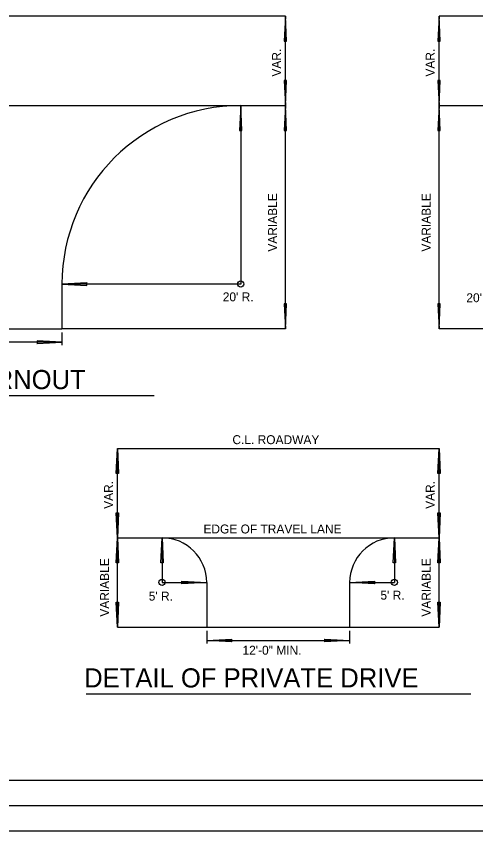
# Model space of a CAD drawing. Extents: x 1944905 to 1956777, y 763871 to 764977.
# Drawn here: x 1947213 to 1947573, y 763871 to 764509 of the extents above; entities that cross this region are included whole.
import ezdxf

# ---------------------------------------------------------------- set-up
doc = ezdxf.new("R2010")
doc.units = 0
doc.layers.add('Default', color=7, linetype='Continuous')
doc.layers.add('E_Existing ROW', color=7, linetype='Continuous')

msp = doc.modelspace()

# ---------------------------------------------------------------- linework, layer by layer
at = {"layer": 'Default'}
for p, q in [((1947423.48, 764509.29), (1946821.48, 764509.29)), ((1947423.48, 764509.29), (1947422.51, 764489.74)), ((1947423.48, 764439.29), (1947423.48, 764509.29)), ((1947424.46, 764489.74), (1947423.48, 764509.29)), ((1947543.85, 764509.29), (1947542.88, 764489.74)), ((1948061.85, 764509.29), (1947543.85, 764509.29)), ((1947543.85, 764439.29), (1947543.85, 764509.29)), ((1947544.83, 764489.74), (1947543.85, 764509.29)), ((1947422.51, 764489.74), (1947424.46, 764489.74)), ((1947424.46, 764489.68), (1947424.46, 764489.74)), ((1947542.88, 764489.74), (1947544.83, 764489.74)), ((1947544.83, 764489.68), (1947544.83, 764489.74)), ((1947422.51, 764458.9), (1947422.51, 764458.84)), ((1947422.51, 764458.84), (1947423.48, 764439.29)), ((1947424.46, 764458.84), (1947422.51, 764458.84)), ((1947423.48, 764439.29), (1947424.46, 764458.84)), ((1947542.88, 764458.9), (1947542.88, 764458.84)), ((1947542.88, 764458.84), (1947543.85, 764439.29)), ((1947544.83, 764458.84), (1947542.88, 764458.84)), ((1947543.85, 764439.29), (1947544.83, 764458.84)), ((1946856.48, 764439.29), (1947388.48, 764439.29)), ((1947388.48, 764439.29), (1947387.51, 764419.74)), ((1947389.46, 764419.74), (1947388.48, 764439.29)), ((1947388.48, 764439.29), (1947388.48, 764299.29)), ((1947423.48, 764439.29), (1947422.51, 764419.74)), ((1947424.46, 764419.74), (1947423.48, 764439.29)), ((1947423.48, 764264.29), (1947423.48, 764438.7)), ((1947543.85, 764439.29), (1947542.88, 764419.74)), ((1947544.83, 764419.74), (1947543.85, 764439.29)), ((1947543.85, 764264.29), (1947543.85, 764438.7)), ((1947387.51, 764419.74), (1947389.46, 764419.74)), ((1947389.46, 764419.68), (1947389.46, 764419.74)), ((1947422.51, 764419.74), (1947424.46, 764419.74)), ((1947424.46, 764419.68), (1947424.46, 764419.74)), ((1947542.88, 764419.74), (1947544.83, 764419.74)), ((1947544.83, 764419.68), (1947544.83, 764419.74)), ((1947268.03, 764300.27), (1947248.48, 764299.29)), ((1947388.48, 764299.29), (1947248.48, 764299.29)), ((1947248.48, 764299.29), (1947268.03, 764298.31)), ((1947268.03, 764298.31), (1947268.03, 764300.27)), ((1947268.1, 764300.27), (1947268.03, 764300.27)), ((1947422.51, 764283.9), (1947422.51, 764283.84)), ((1947422.51, 764283.84), (1947423.48, 764264.29)), ((1947424.46, 764283.84), (1947422.51, 764283.84)), ((1947423.48, 764264.29), (1947424.46, 764283.84)), ((1947542.88, 764283.9), (1947542.88, 764283.84)), ((1947542.88, 764283.84), (1947543.85, 764264.29)), ((1947544.83, 764283.84), (1947542.88, 764283.84)), ((1947543.85, 764264.29), (1947544.83, 764283.84)), ((1946996.48, 764264.29), (1947248.48, 764264.29)), ((1947423.48, 764264.29), (1947248.48, 764264.29)), ((1947718.85, 764264.29), (1947543.85, 764264.29)), ((1947248.48, 764261.29), (1947248.48, 764251.51)), ((1947248.48, 764253.76), (1946996.48, 764253.76)), ((1947228.87, 764252.78), (1947228.94, 764252.78)), ((1947248.48, 764253.76), (1947228.94, 764254.74)), ((1947228.94, 764254.74), (1947228.94, 764252.78)), ((1947228.94, 764252.78), (1947248.48, 764253.76)), ((1946925.27, 764211.94), (1947320.65, 764211.94)), ((1947290.88, 764150.79), (1947291.85, 764170.34)), ((1947291.85, 764170.34), (1947543.85, 764170.34)), ((1947291.85, 764100.34), (1947291.85, 764170.34)), ((1947291.85, 764170.34), (1947292.83, 764150.79)), ((1947542.88, 764150.79), (1947543.85, 764170.34)), ((1947543.85, 764100.34), (1947543.85, 764170.34)), ((1947543.85, 764170.34), (1947544.83, 764150.79)), ((1947292.83, 764150.79), (1947290.88, 764150.79)), ((1947290.88, 764150.73), (1947290.88, 764150.79)), ((1947544.83, 764150.79), (1947542.88, 764150.79)), ((1947542.88, 764150.73), (1947542.88, 764150.79)), ((1947291.85, 764100.34), (1947290.88, 764119.89)), ((1947290.88, 764119.89), (1947292.83, 764119.89)), ((1947292.83, 764119.89), (1947291.85, 764100.34)), ((1947292.83, 764119.95), (1947292.83, 764119.89)), ((1947543.85, 764100.34), (1947542.88, 764119.89)), ((1947542.88, 764119.89), (1947544.83, 764119.89)), ((1947544.83, 764119.89), (1947543.85, 764100.34)), ((1947544.83, 764119.95), (1947544.83, 764119.89)), ((1947290.88, 764080.79), (1947291.85, 764100.34)), ((1947291.85, 764100.34), (1947292.83, 764080.79)), ((1947291.85, 764030.34), (1947291.85, 764099.75)), ((1947325.88, 764080.79), (1947326.85, 764100.34)), ((1947326.85, 764100.34), (1947508.85, 764100.34)), ((1947326.85, 764100.34), (1947327.83, 764080.79)), ((1947326.85, 764100.34), (1947326.85, 764065.34)), ((1947507.88, 764080.79), (1947508.85, 764100.34)), ((1947508.85, 764100.34), (1947508.85, 764065.34)), ((1947508.85, 764100.34), (1947509.83, 764080.79)), ((1947542.88, 764080.79), (1947543.85, 764100.34)), ((1947543.85, 764100.34), (1947544.83, 764080.79)), ((1947543.85, 764030.34), (1947543.85, 764099.75)), ((1947292.83, 764080.79), (1947290.88, 764080.79)), ((1947290.88, 764080.73), (1947290.88, 764080.79)), ((1947327.83, 764080.79), (1947325.88, 764080.79)), ((1947325.88, 764080.73), (1947325.88, 764080.79)), ((1947509.83, 764080.79), (1947507.88, 764080.79)), ((1947507.88, 764080.73), (1947507.88, 764080.79)), ((1947544.83, 764080.79), (1947542.88, 764080.79)), ((1947542.88, 764080.73), (1947542.88, 764080.79)), ((1947326.85, 764065.34), (1947361.85, 764065.34)), ((1947342.24, 764066.32), (1947342.31, 764066.32)), ((1947342.31, 764066.32), (1947361.85, 764065.34)), ((1947342.31, 764064.36), (1947342.31, 764066.32)), ((1947361.85, 764065.34), (1947342.31, 764064.36)), ((1947473.85, 764065.34), (1947493.4, 764066.32)), ((1947473.85, 764065.34), (1947508.85, 764065.34)), ((1947493.4, 764064.36), (1947473.85, 764065.34)), ((1947493.4, 764066.32), (1947493.4, 764064.36)), ((1947493.47, 764064.36), (1947493.4, 764064.36)), ((1947291.85, 764030.34), (1947290.88, 764049.89)), ((1947290.88, 764049.89), (1947292.83, 764049.89)), ((1947292.83, 764049.89), (1947291.85, 764030.34)), ((1947292.83, 764049.95), (1947292.83, 764049.89)), ((1947543.85, 764030.34), (1947542.88, 764049.89)), ((1947542.88, 764049.89), (1947544.83, 764049.89)), ((1947544.83, 764049.89), (1947543.85, 764030.34)), ((1947544.83, 764049.95), (1947544.83, 764049.89)), ((1947291.85, 764030.34), (1947361.85, 764030.34)), ((1947361.85, 764030.34), (1947473.85, 764030.34)), ((1947361.85, 764027.35), (1947361.85, 764017.56)), ((1947473.85, 764030.34), (1947543.85, 764030.34)), ((1947473.85, 764027.35), (1947473.85, 764017.56)), ((1947361.85, 764019.81), (1947381.4, 764020.79)), ((1947381.4, 764018.83), (1947361.85, 764019.81)), ((1947361.85, 764019.81), (1947473.85, 764019.81)), ((1947381.4, 764020.79), (1947381.4, 764018.83)), ((1947454.24, 764020.79), (1947454.31, 764020.79)), ((1947454.31, 764020.79), (1947473.85, 764019.81)), ((1947454.31, 764018.83), (1947454.31, 764020.79)), ((1947473.85, 764019.81), (1947454.31, 764018.83)), ((1947381.47, 764018.83), (1947381.4, 764018.83)), ((1947267.35, 763978), (1947568.77, 763978)), ((1948232.12, 763910.07), (1946651.22, 763910.07)), ((1946618.38, 763890.36), (1948232.12, 763890.36)), ((1946618.38, 763870.67), (1948232.12, 763870.67))]:
    msp.add_line(p, q, dxfattribs=at)
for centre in [(1947388.48, 764299.29), (1947326.85, 764065.34), (1947508.85, 764065.34)]:
    msp.add_circle(centre, 2.44, dxfattribs=at)
at = {"layer": 'E_Existing ROW'}
for p, q in [((1947388.48, 764439.29), (1947423.48, 764439.29)), ((1947543.85, 764439.29), (1947578.85, 764439.29)), ((1947248.48, 764299.29), (1947248.48, 764264.29)), ((1947291.85, 764100.34), (1947326.85, 764100.34)), ((1947508.85, 764100.34), (1947543.85, 764100.34)), ((1947361.85, 764065.34), (1947361.85, 764030.34)), ((1947473.85, 764065.34), (1947473.85, 764030.34))]:
    msp.add_line(p, q, dxfattribs=at)
for centre, radius, start, end in [((1947388.48, 764299.29), 140, 90, 180), ((1947326.85, 764065.34), 35, 0, 90), ((1947508.85, 764065.34), 35, 90, 180)]:
    msp.add_arc(centre, radius, start, end, dxfattribs=at)

# ---------------------------------------------------------------- texts
at = {"layer": 'Default'}
for s, p in [('VAR.', (1947420.06, 764462.01)), ('VAR.', (1947540.43, 764462.01)), ('VARIABLE', (1947416.94, 764324.75)), ('VARIABLE', (1947537.31, 764324.75)), ('VAR.', (1947288.43, 764123.06)), ('VAR.', (1947540.43, 764123.06)), ('VARIABLE', (1947285.31, 764038.5)), ('VARIABLE', (1947537.31, 764038.5))]:
    msp.add_text(s, height=7, rotation=90, dxfattribs=at).set_placement(p)
for s, height, p in [("20' R.", 7, (1947374.43, 764285.79)), ("20' R.", 7, (1947565.27, 764285.09)), ('DETAIL OF CITY STREET TURNOUT', 15, (1946923.81, 764216.94)), ('C.L. ROADWAY', 7, (1947381.98, 764173.79)), ('EDGE OF TRAVEL LANE', 7, (1947359.28, 764103.76)), ("5' R.", 7, (1947316.44, 764051.14)), ("5' R.", 7, (1947497.97, 764051.85)), ('12\'-0" MIN.', 7, (1947389.89, 764008.71)), ('DETAIL OF PRIVATE DRIVE', 15, (1947265.86, 763983))]:
    msp.add_text(s, height=height, dxfattribs=at).set_placement(p)

doc.saveas('drawing.dxf')
